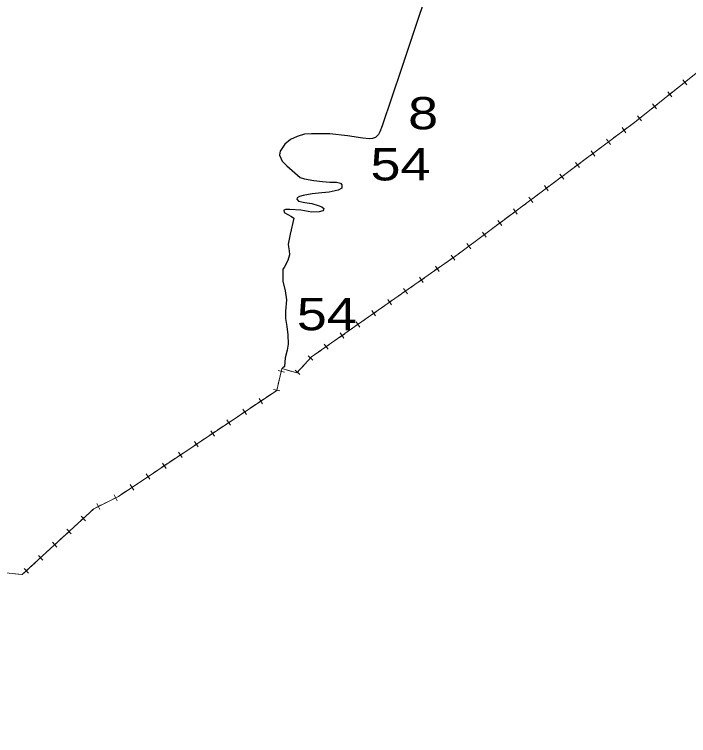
# Model space of a CAD drawing. Extents: x 476989 to 498418, y 4381813 to 4416555.
# Drawn here: x 486617 to 487660, y 4382283 to 4383399 of the extents above; entities that cross this region are included whole.
import ezdxf

# ---------------------------------------------------------------- set-up
doc = ezdxf.new("R2010")
doc.units = 0
doc.header["$LTSCALE"] = 20
for name, color, linetype, lineweight in [('13', 7, 'Continuous', 13), ('34', 7, 'Continuous', 13), ('6', 7, 'Continuous', 25)]:
    doc.layers.add(name, color=color, linetype=linetype, lineweight=lineweight)

msp = doc.modelspace()

# ---------------------------------------------------------------- linework, layer by layer
at = {"layer": '34'}
for p, q in [((487658.55, 4383296.99), (487650.73, 4383290.76)), ((487657.75, 4383289.96), (487651.52, 4383297.78)), ((487646.82, 4383287.64), (487639, 4383281.41)), ((487635.09, 4383278.3), (487627.27, 4383272.07)), ((487634.3, 4383271.27), (487628.07, 4383279.09)), ((487623.36, 4383268.95), (487615.54, 4383262.72)), ((487611.64, 4383259.61), (487603.82, 4383253.37)), ((487610.85, 4383252.58), (487604.61, 4383260.4)), ((487588.19, 4383240.92), (487580.37, 4383234.68)), ((487587.39, 4383233.89), (487581.16, 4383241.71)), ((487599.91, 4383250.26), (487592.09, 4383244.03)), ((487576.44, 4383231.58), (487568.43, 4383225.6)), ((487564.44, 4383222.61), (487556.43, 4383216.63)), ((487563.42, 4383215.61), (487557.44, 4383223.62)), ((487552.42, 4383213.63), (487544.41, 4383207.65)), ((487540.41, 4383204.66), (487532.4, 4383198.67)), ((487539.4, 4383197.66), (487533.41, 4383205.67)), ((487516.39, 4383186.71), (487508.38, 4383180.72)), ((487515.38, 4383179.71), (487509.39, 4383187.72)), ((487528.4, 4383195.68), (487520.39, 4383189.69)), ((487504.37, 4383177.73), (487496.36, 4383171.74)), ((487492.36, 4383168.76), (487484.35, 4383162.77)), ((487491.35, 4383161.76), (487485.37, 4383169.77)), ((487467.33, 4383143.81), (487461.34, 4383151.82)), ((487480.35, 4383159.78), (487472.34, 4383153.79)), ((487456.33, 4383141.83), (487448.31, 4383135.84)), ((487468.34, 4383150.8), (487460.33, 4383144.82)), ((487444.32, 4383132.85), (487436.31, 4383126.87)), ((487443.31, 4383125.85), (487437.32, 4383133.87)), ((487432.3, 4383123.87), (487424.29, 4383117.89)), ((487420.29, 4383114.9), (487412.28, 4383108.92)), ((487419.28, 4383107.9), (487413.3, 4383115.91)), ((487396.27, 4383096.95), (487388.26, 4383090.96)), ((487395.26, 4383089.95), (487389.27, 4383097.96)), ((487408.28, 4383105.92), (487400.27, 4383099.94)), ((487384.25, 4383087.97), (487376.24, 4383081.98)), ((487372.25, 4383079), (487364.24, 4383073.01)), ((487371.23, 4383072), (487365.25, 4383080.01)), ((487360.23, 4383070.02), (487352.22, 4383064.03)), ((487336.21, 4383052.07), (487328.2, 4383046.08)), ((487348.22, 4383061.05), (487340.21, 4383055.06)), ((487347.21, 4383054.05), (487341.22, 4383062.06)), ((487324.2, 4383043.09), (487316.19, 4383037.11)), ((487323.19, 4383036.1), (487317.2, 4383044.11)), ((487312.18, 4383034.12), (487304.17, 4383028.13)), ((487300.09, 4383025.26), (487291.9, 4383019.52)), ((487298.86, 4383018.3), (487293.13, 4383026.49)), ((487275.53, 4383008.06), (487267.34, 4383002.32)), ((487274.3, 4383001.09), (487268.56, 4383009.28)), ((487287.8, 4383016.66), (487279.61, 4383010.92)), ((487263.24, 4382999.45), (487255.05, 4382993.71)), ((487250.96, 4382990.85), (487242.77, 4382985.11)), ((487249.74, 4382983.89), (487244, 4382992.08)), ((487226.4, 4382973.64), (487218.21, 4382967.91)), ((487225.17, 4382966.68), (487219.43, 4382974.87)), ((487238.68, 4382982.24), (487230.49, 4382976.51)), ((487214.11, 4382965.04), (487205.92, 4382959.3)), ((487201.84, 4382956.44), (487193.64, 4382950.7)), ((487200.61, 4382949.48), (487194.87, 4382957.67)), ((487176.04, 4382932.27), (487170.31, 4382940.46)), ((487189.55, 4382947.83), (487181.36, 4382942.1)), ((487164.99, 4382930.63), (487156.79, 4382924.89)), ((487177.27, 4382939.23), (487169.08, 4382933.5)), ((487152.71, 4382922.03), (487144.52, 4382916.29)), ((487151.48, 4382915.06), (487145.74, 4382923.26)), ((487140.42, 4382913.42), (487132.23, 4382907.69)), ((487115.86, 4382896.22), (487107.67, 4382890.48)), ((487128.14, 4382904.82), (487119.95, 4382899.09)), ((487126.92, 4382897.86), (487121.18, 4382906.05)), ((487103.58, 4382887.62), (487095.39, 4382881.88)), ((487102.35, 4382880.65), (487096.62, 4382888.84)), ((487091.29, 4382879.01), (487083.1, 4382873.28)), ((487078.96, 4382863.75), (487071.6, 4382870.52)), ((487068.51, 4382859.77), (487061.74, 4382852.41)), ((487034.84, 4382845.47), (487025.1, 4382847.76)), ((487045.81, 4382846.49), (487036.25, 4382849.4)), ((487058.66, 4382841.68), (487051.3, 4382848.45)), ((487027.68, 4382836.88), (487025.39, 4382827.15)), ((487027.97, 4382816.28), (487018.23, 4382818.57)), ((487015.05, 4382811.68), (487006.74, 4382806.12)), ((486990.13, 4382795), (486981.82, 4382789.43)), ((487002.59, 4382803.34), (486994.28, 4382797.78)), ((487001.22, 4382796.4), (486995.66, 4382804.71)), ((486977.67, 4382786.66), (486969.36, 4382781.09)), ((486976.3, 4382779.72), (486970.73, 4382788.03)), ((486965.21, 4382778.31), (486956.9, 4382772.75)), ((486940.28, 4382761.63), (486931.97, 4382756.07)), ((486952.75, 4382769.97), (486944.44, 4382764.41)), ((486951.38, 4382763.04), (486945.81, 4382771.35)), ((486927.83, 4382753.29), (486919.52, 4382747.73)), ((486926.45, 4382746.36), (486920.89, 4382754.67)), ((486915.36, 4382744.95), (486907.05, 4382739.39)), ((486890.44, 4382728.27), (486882.13, 4382722.7)), ((486902.91, 4382736.61), (486894.6, 4382731.05)), ((486901.53, 4382729.67), (486895.97, 4382737.98)), ((486877.98, 4382719.93), (486869.67, 4382714.37)), ((486876.61, 4382712.99), (486871.05, 4382721.3)), ((486865.52, 4382711.58), (486857.21, 4382706.02)), ((486840.6, 4382694.9), (486832.29, 4382689.34)), ((486853.06, 4382703.25), (486844.75, 4382697.68)), ((486851.69, 4382696.31), (486846.13, 4382704.62)), ((486828.14, 4382686.56), (486819.83, 4382681)), ((486826.77, 4382679.63), (486821.2, 4382687.94)), ((486815.67, 4382678.22), (486807.36, 4382672.66)), ((486790.75, 4382661.54), (486782.44, 4382655.97)), ((486803.22, 4382669.88), (486794.91, 4382664.32)), ((486801.84, 4382662.94), (486796.28, 4382671.25)), ((486776.08, 4382646.45), (486771.61, 4382655.4)), ((486751.49, 4382639.75), (486742.55, 4382635.28)), ((486749.26, 4382633.04), (486744.79, 4382641.98)), ((486764.9, 4382646.45), (486755.96, 4382641.98)), ((486738.42, 4382632.55), (486731.05, 4382625.78)), ((486727.38, 4382622.4), (486720.02, 4382615.64)), ((486727.08, 4382615.34), (486720.32, 4382622.7)), ((486716.34, 4382612.25), (486708.97, 4382605.49)), ((486705.3, 4382602.11), (486697.93, 4382595.35)), ((486705, 4382595.05), (486698.23, 4382602.41)), ((486694.25, 4382591.96), (486686.89, 4382585.2)), ((486672.17, 4382571.67), (486664.81, 4382564.9)), ((486683.22, 4382581.82), (486675.85, 4382575.05)), ((486682.92, 4382574.76), (486676.15, 4382582.12)), ((486661.13, 4382561.53), (486653.77, 4382554.76)), ((486660.83, 4382554.46), (486654.07, 4382561.83)), ((486650.09, 4382551.38), (486642.73, 4382544.61)), ((486639.05, 4382541.24), (486631.69, 4382534.47)), ((486638.75, 4382534.17), (486631.99, 4382541.53)), ((486627.66, 4382532.15), (486617.72, 4382533.23))]:
    msp.add_line(p, q, dxfattribs=at)
for points in [[(487676.62, 4383311.4), (487577, 4383232), (487304, 4383028), (487077, 4382869), (487054, 4382844), (487031, 4382851), (487023, 4382817), (486778, 4382653), (486740, 4382634), (486629, 4382532), (486583, 4382537), (486557, 4382471), (486289, 4382313), (486283, 4382292), (486265, 4382283)], [(487079.02, 4382870.41), (487077, 4382869), (487071.9, 4382863.45)], [(487031.47, 4382850.86), (487031, 4382851), (487028.82, 4382841.75)], [(487058.36, 4382848.74), (487054, 4382844), (487050.6, 4382845.04)], [(487024.24, 4382822.29), (487023, 4382817), (487019.2, 4382814.46)], [(486778.3, 4382653.2), (486778, 4382653), (486769.37, 4382648.69)]]:
    msp.add_lwpolyline(points, dxfattribs=at)
at = {"layer": '6'}
for points in [[(487262.98, 4383453.83), (487243.49, 4383397.09), (487215.9, 4383314.87), (487186.11, 4383226.43), (487182.63, 4383217.34), (487180.29, 4383212.75), (487175.73, 4383208.4), (487171.21, 4383207.02), (487166.04, 4383206.21), (487156.02, 4383207.28), (487132.44, 4383211.07), (487105.23, 4383213.77), (487076.64, 4383213.95), (487066.01, 4383213.3), (487054.41, 4383209.96), (487044.4, 4383205.38), (487035.65, 4383198.23), (487028.06, 4383187.44)], [(487028.33, 4383187.82), (487027.14, 4383181.15), (487031.16, 4383171.92), (487038.79, 4383164.3), (487051.24, 4383153.47), (487059.28, 4383146.25), (487066.11, 4383144.25), (487080.17, 4383141.84), (487093.82, 4383140.24), (487105.07, 4383139.44), (487115.52, 4383139.04), (487121.54, 4383137.43), (487123.55, 4383135.02), (487123.55, 4383129.96), (487117.93, 4383126.75), (487104.27, 4383123.94), (487093.02, 4383122.74), (487077.76, 4383121.13), (487064.1, 4383118.72), (487058.07, 4383117.12), (487054.46, 4383115.11), (487054.05, 4383113.1), (487056.87, 4383109.89), (487066.51, 4383107.88), (487077.35, 4383106.28), (487087, 4383103.07), (487092.62, 4383101.06), (487095.83, 4383098.25), (487095.43, 4383096.24), (487094.23, 4383095.04), (487088.6, 4383093.43), (487077.35, 4383093.03), (487060.08, 4383095.84), (487043.21, 4383097.05), (487036.78, 4383097.05), (487033.97, 4383095.84), (487034.37, 4383092.23), (487045.62, 4383086.21), (487049.64, 4383083.4), (487043.61, 4383058.64), (487040.8, 4383043.38), (487041.2, 4383039.37), (487042.4, 4383032.95), (487042.85, 4383026.65), (487040.03, 4383018.22), (487034.41, 4383006.98), (487032.4, 4383004.57), (487032.4, 4382998.15), (487032.4, 4382986.11), (487036.02, 4382971.02), (487038.03, 4382957.37), (487036.82, 4382939.39), (487036.82, 4382928.15), (487038.83, 4382916.11), (487040.03, 4382902.87), (487040.84, 4382888.42), (487039.23, 4382879.18), (487036.02, 4382867.67), (487034.81, 4382854.02), (487032, 4382851.61)]]:
    msp.add_lwpolyline(points, dxfattribs=at)

# ---------------------------------------------------------------- texts
at = {"layer": '13', "width": 1.25}
for s, p in [('8', (487226.3, 4383221.02)), ('54', (487168.07, 4383141.9)), ('54', (487054.02, 4382910.13))]:
    msp.add_text(s, height=50, dxfattribs=at).set_placement(p)

doc.saveas('drawing.dxf')
